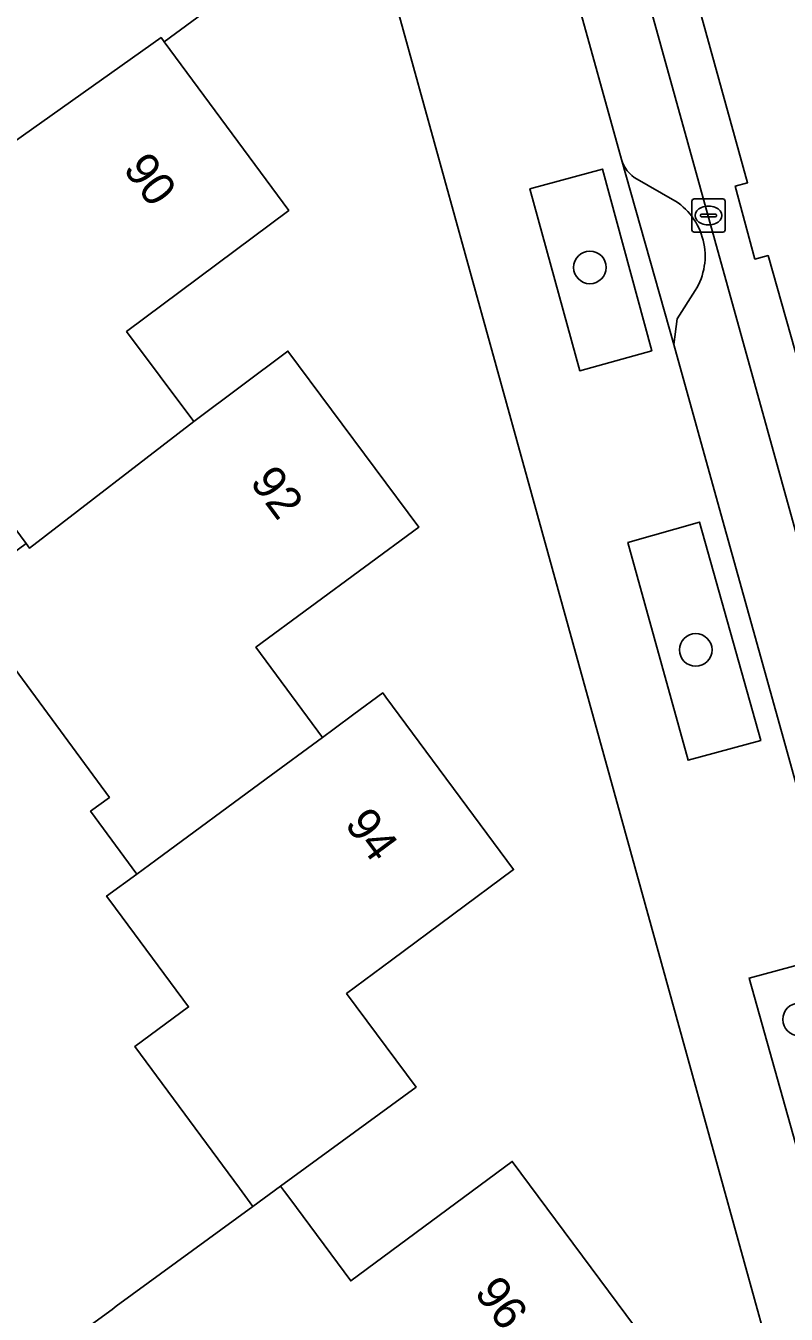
# Model space of a CAD drawing. Extents: x 163426 to 164192, y 380329 to 381641.
# Drawn here: x 163903.53 to 163926.35, y 381284.84 to 381323.49 of the extents above; entities that cross this region are included whole.
import ezdxf

# ---------------------------------------------------------------- set-up
doc = ezdxf.new("R2010")
doc.units = 0
for name, color, linetype in [('IMGEO_Boom', 7, 'Continuous'), ('IMGEO_Erf', 7, 'Continuous'), ('IMGEO_Groenvoorziening', 7, 'Continuous'), ('IMGEO_Kolk', 7, 'Continuous'), ('IMGEO_Pand', 7, 'Continuous'), ('IMGEO_Pand_nummerreeks', 7, 'Continuous'), ('IMGEO_Parkeervlak_open', 7, 'Continuous'), ('IMGEO_Rijbaan_lokaal_gesloten', 7, 'Continuous'), ('IMGEO_Verkeerseiland_open', 7, 'Continuous'), ('IMGEO_Voetpad_open', 7, 'Continuous')]:
    doc.layers.add(name, color=color, linetype=linetype)

msp = doc.modelspace()

# ---------------------------------------------------------------- linework, layer by layer
at = {"layer": 'IMGEO_Boom'}
for centre in [(163920.455, 381316.24), (163923.63, 381304.765), (163926.731, 381293.681)]:
    msp.add_circle(centre, 0.489, dxfattribs=at)
at = {"layer": 'IMGEO_Erf'}
for points in [[(163926.328, 381281.925), (163905.25, 381358.102)], [(163910.667, 381325.204), (163907.69, 381323.004), (163911.424, 381317.95), (163906.56, 381314.314), (163908.572, 381311.622), (163911.395, 381313.731), (163915.324, 381308.444), (163910.439, 381304.843), (163912.43, 381302.14), (163912.786, 381302.402), (163913.375, 381302.836), (163914.24, 381303.474), (163914.335, 381303.345), (163918.167, 381298.176), (163914.504, 381295.455), (163913.159, 381294.456), (163915.244, 381291.65), (163911.179, 381288.677), (163911.296, 381288.519), (163911.451, 381288.309), (163913.281, 381285.836), (163918.129, 381289.422), (163922.057, 381284.127)], [(163903.127, 381307.644), (163903.544, 381307.953), (163900.092, 381312.62)], [(163904.773, 381283.994), (163906.121, 381284.979), (163906.249, 381285.073), (163910.348, 381288.07), (163910.267, 381288.18), (163909.94, 381288.622), (163906.802, 381292.863), (163908.417, 381294.057), (163906.058, 381297.246), (163905.96, 381297.378), (163906.862, 381298.042), (163905.478, 381299.923), (163906.041, 381300.338), (163901.707, 381306.226)]]:
    msp.add_lwpolyline(points, dxfattribs=at)
at = {"layer": 'IMGEO_Groenvoorziening'}
for points in [[(163920.153, 381313.142), (163922.313, 381313.741), (163920.836, 381319.19), (163918.655, 381318.597)], [(163923.403, 381301.453), (163925.582, 381302.046), (163923.748, 381308.6), (163921.595, 381307.988)], [(163928.862, 381281.978), (163931.009, 381282.581), (163927.415, 381295.511), (163925.229, 381294.921)]]:
    msp.add_lwpolyline(points, close=True, dxfattribs=at)
at = {"layer": 'IMGEO_Kolk'}
for p, q in [((163923.513, 381317.371), (163923.513, 381318.223)), ((163923.588, 381318.297), (163924.44, 381318.297)), ((163924.001, 381318.077), (163924.026, 381318.077)), ((163924.514, 381318.223), (163924.514, 381317.371)), ((163923.772, 381317.791), (163923.772, 381317.803)), ((163924.21, 381317.754), (163923.812, 381317.754)), ((163923.815, 381317.84), (163924.213, 381317.84)), ((163924.256, 381317.803), (163924.256, 381317.791)), ((163924.44, 381317.297), (163923.588, 381317.297)), ((163924.024, 381317.517), (163923.999, 381317.517))]:
    msp.add_line(p, q, dxfattribs=at)
for points in [[(163923.513, 381317.371), (163923.513, 381318.223)], [(163923.588, 381318.297), (163924.44, 381318.297)], [(163924.514, 381318.223), (163924.514, 381317.371)], [(163924.44, 381317.297), (163923.588, 381317.297)]]:
    msp.add_lwpolyline(points, dxfattribs=at)
for centre, radius, start, end in [((163923.59, 381318.221), 0.0765, 91.552, 178.448), ((163923.59, 381318.221), 0.0765, 91.552, 178.448), ((163924.438, 381318.221), 0.0765, 1.552, 88.448), ((163924.438, 381318.221), 0.0765, 1.552, 88.448), ((163923.812, 381317.8), 0.0403, 85.8775, 175.7526), ((163923.809, 381317.79), 0.0366, 178.938, 274.7102), ((163924.213, 381317.797), 0.043, 264.8664, 352.4533), ((163924.217, 381317.802), 0.0386, 1.7309, 96.639), ((163923.59, 381317.373), 0.0765, 181.552, 268.448), ((163923.59, 381317.373), 0.0765, 181.552, 268.448), ((163924.438, 381317.373), 0.0765, 271.552, 358.448), ((163924.438, 381317.373), 0.0765, 271.552, 358.448)]:
    msp.add_arc(centre, radius, start, end, dxfattribs=at)
for centre, major_axis, ratio, start_param, end_param in [((163924, 381317.797), (-0.387, 0.002), 0.722429, 4.712389, 7.853982), ((163924.025, 381317.797), (-0.39, 0.002), 0.717154, 1.570796, 4.712389)]:
    msp.add_ellipse(centre, major_axis=major_axis, ratio=ratio, start_param=start_param, end_param=end_param, dxfattribs=at)
at = {"layer": 'IMGEO_Pand'}
for points in [[(163899.862, 381329.594), (163899.77, 381329.719), (163898.976, 381329.132), (163898.886, 381329.254), (163894.685, 381326.146), (163894.775, 381326.025), (163897.658, 381322.126), (163898.334, 381321.213), (163899.94, 381322.402), (163902.216, 381319.325), (163907.595, 381323.133), (163907.69, 381323.004), (163910.667, 381325.204), (163906.744, 381330.506), (163901.854, 381326.895)], [(163908.572, 381311.622), (163906.56, 381314.314), (163911.424, 381317.95), (163907.69, 381323.004), (163907.595, 381323.133), (163902.216, 381319.325), (163899.339, 381316.997), (163901.698, 381313.809), (163900.092, 381312.62), (163903.544, 381307.953), (163903.641, 381307.821)], [(163915.324, 381308.444), (163911.395, 381313.731), (163908.572, 381311.622), (163903.641, 381307.821), (163903.544, 381307.953), (163903.127, 381307.644), (163901.013, 381306.005), (163901.152, 381305.817), (163901.707, 381306.226), (163906.041, 381300.338), (163905.478, 381299.923), (163906.862, 381298.042), (163907.433, 381298.462), (163910.748, 381300.902), (163912.43, 381302.14), (163910.439, 381304.843)], [(163914.335, 381303.345), (163914.24, 381303.474), (163913.375, 381302.836), (163912.786, 381302.402), (163912.43, 381302.14), (163910.748, 381300.902), (163907.433, 381298.462), (163906.862, 381298.042), (163905.96, 381297.378), (163906.058, 381297.246), (163908.417, 381294.057), (163906.802, 381292.863), (163909.94, 381288.622), (163910.267, 381288.18), (163910.348, 381288.07), (163911.179, 381288.677), (163915.244, 381291.65), (163913.159, 381294.456), (163914.504, 381295.455), (163918.167, 381298.176)], [(163911.179, 381288.677), (163910.348, 381288.07), (163906.249, 381285.073), (163906.121, 381284.979), (163904.773, 381283.994), (163907.311, 381280.564), (163910.629, 381276.08), (163910.724, 381275.951), (163918.976, 381282.049), (163919.071, 381281.92), (163922.057, 381284.127), (163918.129, 381289.422), (163913.281, 381285.836), (163911.451, 381288.309), (163911.296, 381288.519)]]:
    msp.add_lwpolyline(points, close=True, dxfattribs=at)
at = {"layer": 'IMGEO_Parkeervlak_open'}
for points in [[(163912.156, 381357.786), (163911.449, 381356.413), (163911.39, 381356.014), (163911.38, 381355.63), (163912.802, 381350.5), (163914.816, 381343.233), (163916.635, 381336.671), (163919.989, 381324.572), (163921.4, 381319.482)], [(163930.967, 381292.691), (163914.635, 381351.57)], [(163921.87, 381318.883), (163922.937, 381318.282)], [(163923.615, 381315.543), (163923.072, 381314.695), (163922.976, 381313.928), (163924.388, 381308.852), (163926.206, 381302.318), (163928.036, 381295.741), (163928.165, 381295.278)]]:
    msp.add_lwpolyline(points, dxfattribs=at)
for centre, radius, start, end in [((163922.379, 381319.767), 1.02, 196.2008, 240.0376), ((163921.943, 381316.583), 1.969, 328.1317, 59.6748)]:
    msp.add_arc(centre, radius, start, end, dxfattribs=at)
at = {"layer": 'IMGEO_Rijbaan_lokaal_gesloten'}
for points in [[(163911.825, 381360.508), (163912.249, 381359.295), (163913.697, 381359.629), (163921.907, 381330.645), (163925.185, 381318.778), (163924.817, 381318.679), (163925.405, 381316.489), (163925.802, 381316.596), (163930.68, 381299.334), (163933.228, 381290.176), (163942.098, 381254.961)], [(163947.265, 381217.038), (163948.882, 381217.269), (163946.144, 381233.78), (163944.552, 381243.335), (163944.183, 381245.1), (163943.726, 381245.01), (163943.287, 381247.227), (163943.722, 381247.313), (163942.098, 381254.961), (163933.228, 381290.176), (163930.68, 381299.334), (163925.802, 381316.596), (163925.405, 381316.489), (163924.817, 381318.679), (163925.185, 381318.778), (163921.907, 381330.645), (163913.697, 381359.629), (163912.249, 381359.295), (163912.307, 381359.162), (163912.358, 381358.996)], [(163914.635, 381351.57), (163930.967, 381292.691), (163932.412, 381287.566), (163932.782, 381286.384), (163932.821, 381286.139)]]:
    msp.add_lwpolyline(points, dxfattribs=at)
at = {"layer": 'IMGEO_Verkeerseiland_open'}
for points in [[(163921.4, 381319.482), (163922.976, 381313.928), (163923.072, 381314.695), (163923.615, 381315.543)], [(163922.937, 381318.282), (163921.87, 381318.883)]]:
    msp.add_lwpolyline(points, dxfattribs=at)
for centre, radius, start, end in [((163922.379, 381319.767), 1.02, 196.2008, 240.0376), ((163921.943, 381316.583), 1.969, 328.1317, 59.6748)]:
    msp.add_arc(centre, radius, start, end, dxfattribs=at)
at = {"layer": 'IMGEO_Voetpad_open'}
for points in [[(163903.594, 381363.274), (163905.25, 381358.102), (163926.328, 381281.925)], [(163928.165, 381295.278), (163928.036, 381295.741), (163926.206, 381302.318), (163924.388, 381308.852), (163922.976, 381313.928), (163921.4, 381319.482), (163919.989, 381324.572), (163916.635, 381336.671)]]:
    msp.add_lwpolyline(points, dxfattribs=at)
for points in [[(163922.313, 381313.741), (163920.153, 381313.142), (163918.655, 381318.597), (163920.836, 381319.19)], [(163923.748, 381308.6), (163925.582, 381302.046), (163923.403, 381301.453), (163921.595, 381307.988)], [(163927.415, 381295.511), (163931.009, 381282.581), (163928.862, 381281.978), (163925.229, 381294.921)]]:
    msp.add_lwpolyline(points, close=True, dxfattribs=at)

# ---------------------------------------------------------------- texts
at = {"layer": 'IMGEO_Pand_nummerreeks'}
for s, rotation, p in [('90', 306.4578, (163906.43, 381319.19)), ('92', 306.6175, (163910.233, 381309.798)), ('94', 306.5488, (163913.076, 381299.536)), ('96', 306.5717, (163916.966, 381285.484))]:
    msp.add_text(s, height=1, rotation=rotation, dxfattribs=at).set_placement(p)

doc.saveas('drawing.dxf')
